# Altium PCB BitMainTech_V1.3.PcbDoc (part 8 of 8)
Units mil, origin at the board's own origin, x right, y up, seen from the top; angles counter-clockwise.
Board outline 9842.52 x 6082.68 mil, 4 copper layers (Top Layer, Mid-Layer 1, Mid-Layer 2, Bottom Layer); 987 components, 282 nets, 3694 pads, 3174 vias.
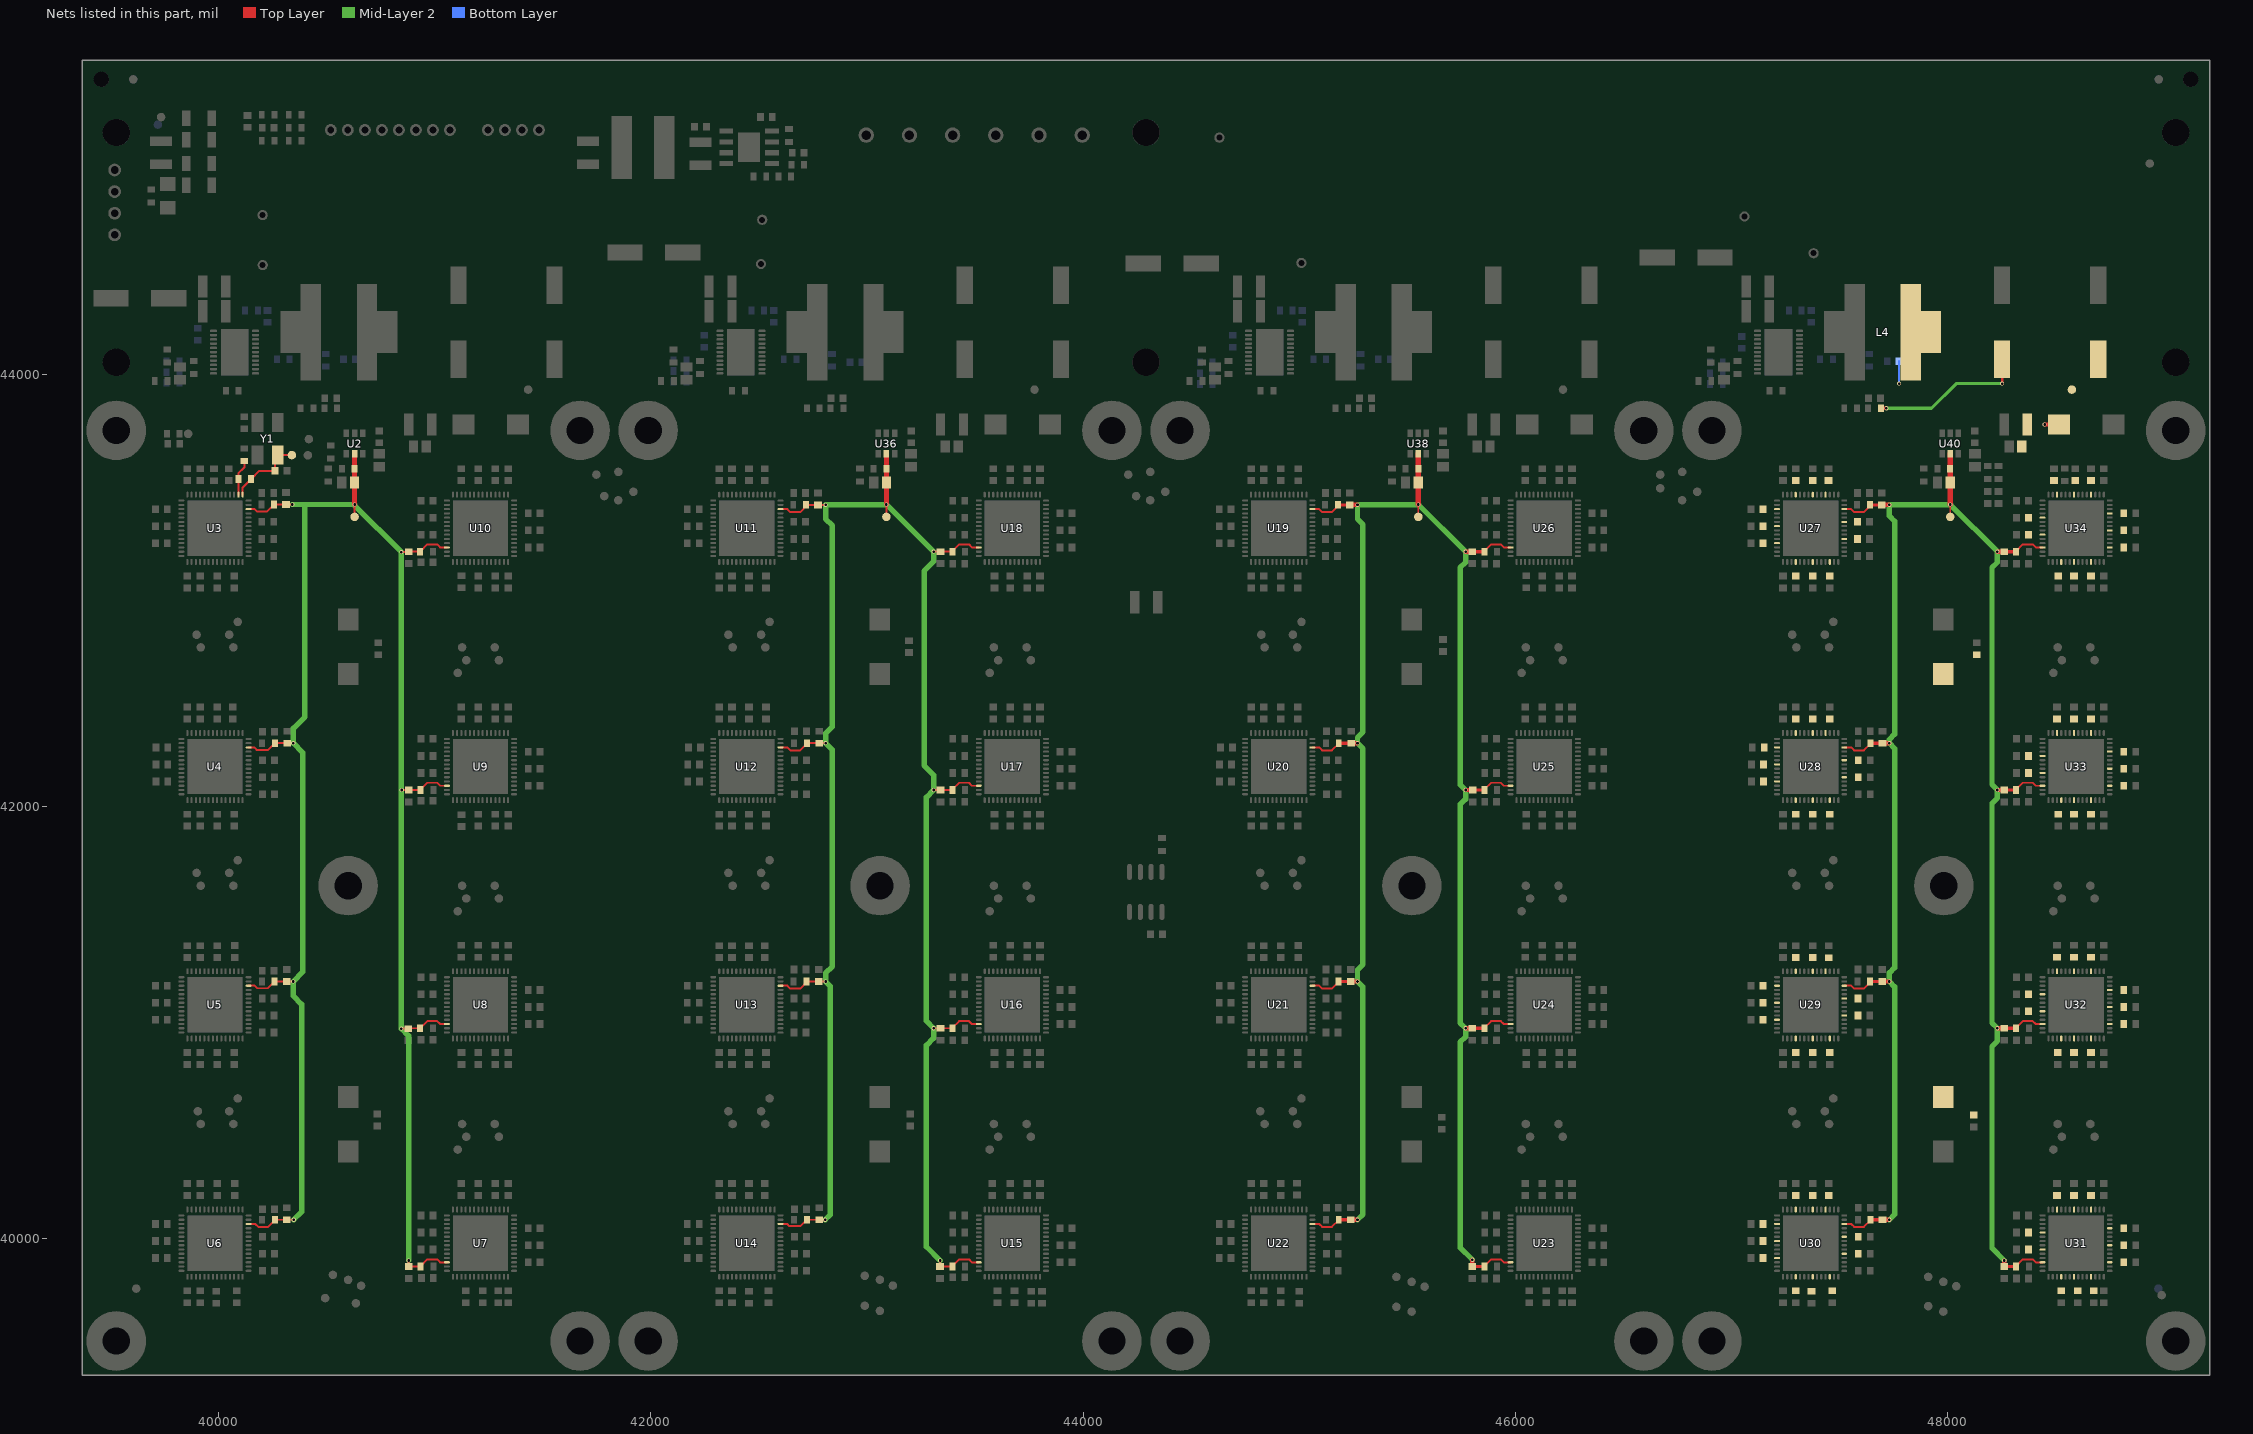
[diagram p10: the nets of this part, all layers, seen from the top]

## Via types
v1: diameter 19, hole 12, Top Layer to Bottom Layer, 1347 vias
v2: diameter 25.98, hole 12.99, Top Layer to Bottom Layer, 800 vias
v3: diameter 24, hole 16, Top Layer to Bottom Layer, 778 vias
v4: diameter 50, hole 28, Top Layer to Bottom Layer, 160 vias
v5: diameter 19.68, hole 11.81, Top Layer to Bottom Layer, 84 vias
v6: diameter 26, hole 18, Top Layer to Bottom Layer, 5 vias

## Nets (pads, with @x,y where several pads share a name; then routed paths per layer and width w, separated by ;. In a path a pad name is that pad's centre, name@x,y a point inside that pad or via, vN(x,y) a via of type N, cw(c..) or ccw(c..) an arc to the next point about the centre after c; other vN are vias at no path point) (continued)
VDD4: C416.1 C417.1 C418.2 C419.2 C440.2 C441.2 C442.2 C443.2 C444.2 C445.2 C446.2 C447.2 C448.2 C449.2 C450.2 C451.2 C452.2 C453.2 C454.2 C455.2 C456.2 C457.2 C458.2 C459.2 C460.2 C461.2 C462.2 C463.2 C464.2 C465.2 C466.2 C467.2 C468.2 C469.2 C470.2 C471.2 C472.2 C473.2 C474.2 C475.2 C476.2 C477.2 C478.2 C479.2 C480.2 C481.2 C482.2 C483.2 C504.2 C505.2 C506.2 C507.2 C508.2 C509.2 C510.2 C511.2 C512.2 C513.2 C514.2 C515.2 C516.2 C517.2 C518.2 C519.2 C520.2 C521.2 C522.2 C523.2 C524.2 C525.2 C526.2 C527.2 C528.2 C529.2 C530.2 C531.2 C532.2 C533.2 C534.2 C535.2 C536.2 C537.2 C538.2 C539.2 C540.2 C541.2 C542.2 C543.2 C544.2 C545.2 C546.2 C547.2 C580.1 C581.1 C582.1 C583.1 C587.2 C588.2 L4.2 R52.1 TP172.1 U27.4 U27.7 U27.11 U27.17 U27.21 U27.25 U27.32 U27.36 U27.40 U27.47 U27.51 U28.4 U28.7 U28.11 U28.17 U28.21 U28.25 U28.32 U28.36 U28.40 U28.47 U28.51 U29.4 U29.7 U29.11 U29.17 U29.21 U29.25 U29.32 U29.36 U29.40 U29.47 U29.51 U30.4 U30.7 U30.11 U30.17 U30.21 U30.25 U30.32 U30.36 U30.40 U30.47 U30.51 U31.4 U31.7 U31.11 U31.17 U31.21 U31.25 U31.32 U31.36 U31.40 U31.47 U31.51 U32.4 U32.7 U32.11 U32.17 U32.21 U32.25 U32.32 U32.36 U32.40 U32.47 U32.51 U33.4 U33.7 U33.11 U33.17 U33.21 U33.25 U33.32 U33.36 U33.40 U33.47 U33.51 U34.4 U34.7 U34.11 U34.17 U34.21 U34.25 U34.32 U34.36 U34.40 U34.47 U34.51 | length 845.5
  Top Layer w11: v1(48251.97,43956.69) C582.1@48251.97,44023.62
  Top Layer w15: R52.1@47690.94,43842.52 v1(47716.54,43842.52)
  Top Layer w20: v1(48448.82,43767.72) C583.1@48515.75,43767.72
  Mid-Layer 2 w15: v1(47716.54,43842.52) 47925.2,43842.52 48039.37,43956.69 v1(48251.97,43956.69)
  Bottom Layer w10: v1(47775.59,43956.69) C580.1@47775.59,44060
VPLL1: C16.2 C21.1 C23.1 C25.1 C27.1 C88.1 C90.1 C92.1 C94.1 FB1.2 FB2.2 FB3.2 FB4.2 FB5.2 FB6.2 FB7.2 FB8.2 R13.2 TP167.1 U2.5 U3.54 U4.54 U5.54 U6.54 U7.54 U8.54 U9.54 U10.54 | length 9395.2
  Top Layer w8: TP167.1@40629.92,43340 v1(40629.92,43397.64)
  Top Layer w9: U6.54@40139.76,40068.9 40171.26,40068.9 40185.04,40055.12 40230.32,40055.12 40263.78,40088.58 C27.1@40316.93,40088.58 v1(40348.43,40088.58) ; U5.54@40139.76,41171.26 40167.32,41171.26 40179.13,41159.45 40228.35,41159.45 FB3.2@40259.84,41190.94 ; U4.54@40139.76,42273.62 40165.35,42273.62 40177.17,42261.81 40230.32,42261.81 FB2.2@40261.81,42293.31 40314.96,42293.31 C90.1@40318.9,42293.31 v1(40346.46,42293.31) ; U3.54@40139.76,43375.98 40167.32,43375.98 40179.13,43364.17 40224.41,43364.17 FB1.2@40257.87,43397.64 40311.02,43397.64 C21.1@40312.99,43397.64 v1(40342.52,43397.64) ; FB3.2@40253.94,41190.94 40307.09,41190.94 v1(40346.46,41190.94) ; v1(40846.46,40972.44) C25.1@40877.95,40972.44 ; v1(40846.46,43177.17) C88.1@40877.95,43177.17 ; v1(40848.43,42076.77) C23.1@40879.92,42076.77 40933.07,42076.77 40966.54,42110.24 41011.81,42110.24 41025.59,42096.46 U9.54@41057.09,42096.46 ; C25.1@40877.95,40974.41 40879.92,40974.41 FB6.2@40933.07,40974.41 40966.54,41007.87 41011.81,41007.87 41025.59,40994.09 U8.54@41057.09,40994.09 ; v1(40879.92,39900) C94.1@40879.92,39872.05 40933.07,39872.05 40966.54,39905.51 41011.81,39905.51 41025.59,39891.73 U7.54@41057.09,39891.73 ; C88.1@40879.92,43179.13 FB8.2@40933.07,43179.13 40966.54,43212.6 41011.81,43212.6 41025.59,43198.82 U10.54@41057.09,43198.82
  Top Layer w24: v1(40629.92,43397.64) C16.2@40629.92,43500 R13.2@40629.92,43562.99 U2.5@40629.92,43631.89
  Mid-Layer 2 w25: v1(40342.52,43397.64) 40400,43397.64 ; v1(40348.43,40088.58) 40385,40125.16 40385,41085 40346.46,41123.54 v1(40346.46,41190.94) 40390,41234.49 40390,42249.76 v1(40346.46,42293.31) 40346.46,42361.46 40400,42415 40400,43397.64 ; v1(40879.92,39900) 40879.92,40938.98 v1(40846.46,40972.44) v1(40846.46,43177.17) 40629.92,43393.7 v1(40629.92,43397.64) 40400,43397.64
VPLL2: C156.1 C158.1 C160.1 C162.1 C220.1 C222.1 C224.1 C226.1 C563.2 FB9.2 FB10.2 FB11.2 FB12.2 FB13.2 FB14.2 FB15.2 FB16.2 R34.2 TP129.1 U11.54 U12.54 U13.54 U14.54 U15.54 U16.54 U17.54 U18.54 U36.5 | length 9460.3
  Top Layer w8: TP129.1@43090.55,43340 v1(43090.55,43397.64)
  Top Layer w9: U14.54@42600.39,40068.9 42631.1,40068.9 42641,40059 42692.86,40059 FB12.2@42722.44,40088.58 42775.59,40088.58 C162.1@42779.53,40088.58 v1(42807.09,40088.58) ; U13.54@42600.39,41171.26 42631.89,41171.26 42645.67,41157.48 42690.94,41157.48 42724.41,41190.94 C224.1@42777.56,41190.94 v1(42809.06,41190.94) ; U12.54@42600.39,42273.62 42631.89,42273.62 42645.67,42259.84 42690.94,42259.84 42724.41,42293.31 C222.1@42777.56,42293.31 ; U11.54@42600.39,43375.98 42631.89,43375.98 42645.67,43362.2 42690.94,43362.2 42724.41,43395.67 42777.56,43395.67 v1(42809.06,43395.67) ; C222.1@42779.53,42293.31 v1(42809.06,42293.31) ; v1(43309.05,40974.41) C160.1@43340.55,40974.41 43393.7,40974.41 43427.17,41007.87 43472.44,41007.87 43486.22,40994.09 U16.54@43517.72,40994.09 ; v1(43309.05,42076.77) C158.1@43340.55,42076.77 43393.7,42076.77 43427.17,42110.24 43472.44,42110.24 43486.22,42096.46 U17.54@43517.72,42096.46 ; v1(43309.05,43179.13) C220.1@43340.55,43179.13 43393.7,43179.13 43427.17,43212.6 43472.44,43212.6 43486.22,43198.82 U18.54@43517.72,43198.82 ; C226.1@43338.58,39872.05 v1(43338.58,39900) ; C226.1@43340.55,39872.05 43393.7,39872.05 43427.17,39905.51 43472.44,39905.51 43486.22,39891.73 U15.54@43517.72,39891.73
  Top Layer w24: v1(43090.55,43397.64) C563.2@43090.55,43500 R34.2@43090.55,43562.99 U36.5@43090.55,43631.89
  Mid-Layer 2 w25: v1(42807.09,40088.58) 42830,40111.5 42830,41170 v1(42809.06,41190.94) 42809.06,41229.06 42840,41260 42840,42262.36 v1(42809.06,42293.31) 42809.06,42339.06 42840,42370 42840,43300 42809.06,43330.94 v1(42809.06,43395.67) v1@43092.52,43395.67 ; v1(43090.55,43397.64) v1@43092.52,43395.67 ; v1(43338.58,39900) 43275,39963.58 43275,40895 43309.05,40929.05 v1(43309.05,40974.41) 43275,41008.46 43275,42042.72 v1(43309.05,42076.77) 43309.05,42145.95 43265,42190 43265,43090 43309.05,43134.05 v1(43309.05,43179.13) v1@43092.52,43395.67
VPLL3: C288.1 C290.1 C292.1 C294.1 C352.1 C354.1 C356.1 C358.1 C579.2 FB17.2 FB18.2 FB19.2 FB20.2 FB21.2 FB22.2 FB23.2 FB24.2 R48.2 TP171.1 U19.54 U20.54 U21.54 U22.54 U23.54 U24.54 U25.54 U26.54 U38.5 | length 9428.2
  Top Layer w8: TP171.1@45551.18,43340 v1(45551.18,43397.64)
  Top Layer w9: U22.54@45061.02,40068.9 45092.52,40068.9 45106.3,40055.12 45151.57,40055.12 FB20.2@45185.04,40088.58 ; U21.54@45061.02,41171.26 45092.52,41171.26 45106.3,41157.48 45151.57,41157.48 FB19.2@45185.04,41190.94 ; U20.54@45061.02,42273.62 45092.52,42273.62 45106.3,42259.84 45151.57,42259.84 FB18.2@45185.04,42293.31 ; U19.54@45061.02,43375.98 45092.52,43375.98 45106.3,43362.2 45151.57,43362.2 FB17.2@45185.04,43395.67 ; FB21.2@45854.33,39872.05 45887.8,39905.51 45933.07,39905.51 45946.85,39891.73 U23.54@45978.35,39891.73 ; FB22.2@45854.33,40974.41 45887.8,41007.87 45933.07,41007.87 45946.85,40994.09 U24.54@45978.35,40994.09 ; FB23.2@45854.33,42076.77 45887.8,42110.24 45933.07,42110.24 45946.85,42096.46 U25.54@45978.35,42096.46 ; FB24.2@45854.33,43179.13 45887.8,43212.6 45933.07,43212.6 45946.85,43198.82 U26.54@45978.35,43198.82
  Top Layer w15: FB20.2@45185.04,40088.58 C294.1@45238.17,40088.58 ; FB19.2@45185.04,41190.94 C356.1@45238.17,41190.94 ; FB18.2@45185.04,42293.31 C354.1@45238.19,42293.31 ; FB17.2@45185.04,43395.67 C288.1@45238.19,43395.67 ; C358.1@45801.16,39872.05 FB21.2@45854.33,39872.05 ; C292.1@45801.16,40974.41 FB22.2@45854.33,40974.41 ; C290.1@45801.18,42076.77 FB23.2@45854.33,42076.77 ; C352.1@45801.16,43179.13 FB24.2@45854.33,43179.13
  Top Layer w20: C294.1@45238.17,40088.58 v1(45269.69,40088.58) ; C356.1@45238.17,41190.94 v1(45269.69,41190.94) ; C288.1@45238.19,43395.67 v1(45269.69,43395.67) ; C354.1@45240.14,42293.31 v1(45269.69,42293.31) ; v1(45769.68,40974.41) C292.1@45801.16,40974.41 ; v1(45769.68,42076.77) C290.1@45801.18,42076.77 ; v1(45769.68,43179.13) C352.1@45801.16,43179.13 ; C358.1@45801.16,39872.05 v1(45801.16,39903.54)
  Top Layer w25: v1(45551.18,43397.64) C579.2@45551.18,43500 R48.2@45551.18,43562.99 U38.5@45551.18,43631.89
  Mid-Layer 2 w25: v1(45269.69,40088.58) 45295,40113.9 45295,41165.63 v1(45269.69,41190.94) 45269.69,41244.69 45295,41270 45295,42267.99 v1(45269.69,42293.31) 45269.69,42319.69 45295,42345 45295,43305 45269.69,43330.31 v1(45269.69,43395.67) v1@45553.15,43395.67 ; v1(45551.18,43397.64) v1@45553.15,43395.67 ; v1(45801.16,39903.54) 45745,39959.71 45745,40910 45769.68,40934.68 v1(45769.68,40974.41) 45745,40999.09 45745,42010 45769.68,42034.68 v1(45769.68,42076.77) 45745,42101.46 45745,43105 45769.68,43129.68 v1(45769.68,43179.13) v1@45553.15,43395.67
VPLL4: C420.1 C422.1 C424.1 C426.1 C484.1 C486.1 C488.1 C490.1 C595.2 FB25.2 FB26.2 FB27.2 FB28.2 FB29.2 FB30.2 FB31.2 FB32.2 R62.2 TP175.1 U27.54 U28.54 U29.54 U30.54 U31.54 U32.54 U33.54 U34.54 U40.5 | length 9430.2
  Top Layer w8: TP175.1@48011.81,43340 v1(48011.81,43397.64)
  Top Layer w9: U30.54@47521.65,40068.9 47553.15,40068.9 47566.93,40055.12 47612.2,40055.12 FB28.2@47645.67,40088.58 ; U29.54@47521.65,41171.26 47553.15,41171.26 47566.93,41157.48 47612.2,41157.48 FB27.2@47645.67,41190.94 ; U28.54@47521.65,42273.62 47553.15,42273.62 47566.93,42259.84 47612.2,42259.84 FB26.2@47645.67,42293.31 ; U27.54@47521.65,43375.98 47553.15,43375.98 47566.93,43362.2 47612.2,43362.2 FB25.2@47645.67,43395.67 ; FB29.2@48314.96,39872.05 48348.43,39905.51 48393.7,39905.51 48407.48,39891.73 U31.54@48438.98,39891.73 ; FB30.2@48314.96,40974.41 48348.43,41007.87 48393.7,41007.87 48407.48,40994.09 U32.54@48438.98,40994.09 ; FB31.2@48314.96,42076.77 48348.43,42110.24 48393.7,42110.24 48407.48,42096.46 U33.54@48438.98,42096.46 ; FB32.2@48314.96,43179.13 48348.43,43212.6 48393.7,43212.6 48407.48,43198.82 U34.54@48438.98,43198.82
  Top Layer w15: FB28.2@47645.67,40088.58 C426.1@47698.82,40088.58 ; FB27.2@47645.67,41190.94 C488.1@47698.82,41190.94 ; FB26.2@47645.67,42293.31 C486.1@47698.82,42293.31 ; FB25.2@47645.67,43395.67 C420.1@47698.82,43395.67 ; C490.1@48261.81,39872.05 FB29.2@48314.96,39872.05 ; C424.1@48261.81,40974.41 FB30.2@48314.96,40974.41 ; C422.1@48261.81,42076.77 FB31.2@48314.96,42076.77 ; C484.1@48261.81,43179.13 FB32.2@48314.96,43179.13
  Top Layer w20: C426.1@47698.82,40088.58 v1(47730.32,40088.58) ; C488.1@47698.82,41190.94 v1(47730.32,41190.94) ; C486.1@47698.82,42293.31 v1(47730.32,42293.31) ; C420.1@47698.82,43395.67 v1(47730.32,43395.67) ; v1(48230.31,40974.41) C424.1@48261.81,40974.41 ; v1(48230.31,42076.77) C422.1@48261.81,42076.77 ; v1(48230.31,43179.13) C484.1@48261.81,43179.13 ; C490.1@48261.81,39872.05 v1(48261.81,39900)
  Top Layer w25: v1(48011.81,43397.64) C595.2@48011.81,43500 R62.2@48011.81,43562.99 U40.5@48011.81,43631.89
  Mid-Layer 2 w25: v1(47730.32,40088.58) 47755,40113.27 47755,41166.26 v1(47730.32,41190.94) 47730.32,41230.32 47755,41255 47755,42268.62 v1(47730.32,42293.31) 47730.32,42310.32 47755,42335 47755,43320 47730.32,43344.68 v1(47730.32,43395.67) v1@48013.78,43395.67 ; v1(48011.81,43397.64) v1@48013.78,43395.67 ; v1(48261.81,39900) 48205,39956.81 48205,40890 48230.31,40915.31 v1(48230.31,40974.41) 48205,40999.72 48205,42015 48230.31,42040.31 v1(48230.31,42076.77) 48205,42102.09 48205,43105 48230.31,43130.31 v1(48230.31,43179.13) v1@48013.78,43395.67
XIN: C29.1 R16.2 TP25.1 U3.1 Y1.1 | length 340.3
  Top Layer w10: U3.1@40112.2,43442.91 40112.2,43476.38 R16.2@40151.57,43515.75 40188.98,43553.15 C29.1@40261.81,43553.15 Y1.1@40261.81,43614.17 ; Y1.1@40275.59,43625.98 TP25.1@40340,43625.98
XOUT: R16.1 R17.1 U3.2 | length 166.9
  Top Layer w10: U3.2@40092.52,43442.91 R16.1@40092.52,43515.75 40092.52,43541.34 40120.08,43568.9 R17.1@40120.08,43598.43
pads on no net: M1.0 M2.0 M3.0 M27.0 M28.0 M32.0 MAKE1.0 MAKE2.0 MAKE3.0 MAKE4.0 MAKE5.0 MAKE6.0 MAKE7.0 MAKE8.0 MAKE9.0 MAKE10.0 U1.5 U3.44 U3.48 U3.49 U4.2 U4.44 U4.48 U4.49 U5.2 U5.44 U5.48 U5.49 U6.2 U6.44 U6.48 U6.49 U7.2 U7.44 U7.48 U7.49 U8.2 U8.44 U8.48 U8.49 U9.2 U9.44 U9.48 U9.49 U10.2 U10.44 U10.48 U10.49 U11.2 U11.44 U11.48 U11.49 U12.2 U12.44 U12.48 U12.49 U13.2 U13.44 U13.48 U13.49 U14.2 U14.44 U14.48 U14.49 U15.2 U15.44 U15.48 U15.49 U16.2 U16.44 U16.48 U16.49 U17.2 U17.44 U17.48 U17.49 U18.2 U18.44 U18.48 U18.49 U19.2 U19.44 U19.48 U19.49 U20.2 U20.44 U20.48 U20.49 U21.2 U21.44 U21.48 U21.49 U22.2 U22.44 U22.48 U22.49 U23.2 U23.44 U23.48 U23.49 U24.2 U24.44 U24.48 U24.49 U25.2 U25.44 U25.48 U25.49 U26.2 U26.44 U26.48 U26.49 U27.2 U27.44 U27.48 U27.49 U28.2 U28.44 U28.48 U28.49 U29.2 U29.44 U29.48 U29.49 U30.2 U30.44 U30.48 U30.49 U31.2 U31.44 U31.48 U31.49 U32.2 U32.44 U32.48 U32.49 U33.2 U33.44 U33.48 U33.49 U34.2 U34.33 U34.34 U34.38 U34.39 U34.44 U37.5 U39.5 U41.5 U42.3 Y1.2 Y1.4

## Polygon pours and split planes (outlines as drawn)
VDD2 on Top Layer "GND1" (solid, remove dead copper, pour order 32): 42960,44420 43155,44420 43350.63,44224.37 44225.63,44224.37 44275,44175 44275,39385 41845,39385 41845,43885 42905,43885 42960,43940
GND on Top Layer "GND1" (solid, remove dead copper, pour order 31): 49200,45260 47155,45260 47155,44085 46865,44085 46785,44165 46785,44470 46620,44635 44935,44635 44800,44500 44800,44085 44460,44085 44460,44420 44245,44635 42500,44635 42355,44490 42355,44090 42010,44090 42010,44495 41870,44635 40150,44635 40010,44495 40010,44080 39625,44080 39625,44705 39390,44705 39390,43910 40590,43910 40605,43925 40605,44440 40790,44440 40990,44240 41679.25,44240 41845,44074.25 41845,43910 42910,43910 42945,43945 42945,44435 43160,44435 43355,44240 44230.79,44240 44378.78,44092.01 44378.78,44040.79 44305,43967.01 44305,43915 45355,43915 45385,43945 45385,44435 45715,44435 45910,44240 46570,44240 46765,44045 46765,43910 47710,43910 47745,43945 47745,44435 47990,44435 48185,44240 49200,44240
+12V on Top Layer "GND1" (solid, remove dead copper, pour order 30): 47140,45259.28 47140,44095 46875,44095 46800,44170 46800,44475 46625,44650 44930,44650 44785,44505 44785,44095 44475.24,44095 44475,44095.24 44475,44425 44250,44650 42490,44650 42340,44500 42340,44095 42330,44105 42025,44105 42025,44500 41875,44650 40145,44650 39995,44500 39995,44095 39640,44095 39640,44550 39640,44551.11 39915,44826.11 39915,45010 40560,45010 40600,45050 41475,45050 41615,44910 41755,44910 41810,44855 42740,44855 42740,45259.28
FANGND on Top Layer "GND1" (solid, pour order 25): 39885,45260 39885,45040 39675,45040 39650,45015 39650,44925 39625,44900 39390,44900 39390,45260
GND on Top Layer "GND1" (solid, pour order 24): 42725,45260 42725,44870 41815,44870 41760,44925 41620,44925 41475,45070 40600,45070 40555,45025 39915,45025 39915,45250 39915,45255 39915,45260
VDD1 on Top Layer "GND1" (solid, remove dead copper, pour order 23): 40620,44425 40785,44425 40985,44225 41665,44225 41815,44075 41815,39385 39385,39385 39385,43885 40595,43885 40620,43910 40620,44425
VDD3 on Top Layer "GND1" (solid, remove dead copper, pour order 22): 44305,43885 45345,43885 45400,43940 45400,44420 45711.26,44420 45906.26,44225 46565,44225 46735,44055 46735,39385 44305,39385
LL2 on Top Layer "GND1" (solid, pour order 21): 42820,43970 42820,44420.16 42818.9,44421.26 42626.26,44421.26 42495,44290 42496.06,44288.94 42496.06,44096.46 42718.54,44096.46 42720,44095 42720,43970
NetC549_2 on Top Layer "GND1" (solid, pour order 18): 39885,45020 39680,45020 39670,45010 39670,44925 39670,44920 39670,44915 39640,44885 39460,44885 39460,44805 39625,44805 39660,44840 39885,44840
VDD4 on Top Layer "GND1" (solid, remove dead copper, pour order 19): 49195,44225 49200,44220 49200,39385 46770,39385 46770,43885 47710,43885 47760,43935 47760,44420 47985,44420 48180,44225
no net on Top Layer "GND1" (solid, pour order 20): 49212.6,45452.76 49212.6,45275.59 39370.08,45275.59 39370.08,45452.76
GND on Mid-Layer 2 "GND1" (solid, remove dead copper, pour order 27): 39385,44085 40010,44085 40010,44495 40150,44635 41870,44635 42010,44495 42010,44100 42355,44100 42355,44490 42500,44635 44245,44635 44460,44420 44460,44085 44800,44085 44800,44500 44935,44635 46620,44635 46785,44470 46785,44165 46865,44085 47155,44085 47155,45260 49200,45260 49200,39385 39385,39385
+12V on Mid-Layer 2 "GND1" (solid, remove dead copper, pour order 26): 39995,44100 39385,44100 39385,45260 47140,45260 47140,44100 46870,44100 46800,44170 46800,44475 46625,44650 44930,44650 44785,44505 44785,44100 44475,44100 44475,44425 44250,44650 42490,44650 42340,44500 42340,44115 42025,44115 42025,44500 41875,44650 40145,44650 39995,44500 39995,44100
GND on Mid-Layer 1 "GND1" (solid, pour order 28): 39370.08,45275.59 49212.6,45275.59 49212.6,39370.08 39370.08,39370.08
GND on Bottom Layer "GND1" (solid, remove dead copper, pour order 29): 39370.08,45275.59 49212.6,45275.59 49212.6,39370.08 39370.08,39370.08
no net on Bottom Layer "GND1" (solid, pour order 17): 39370.08,45452.76 49212.6,45452.76 49212.6,45275.59 39370.08,45275.59

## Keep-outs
Keep-Out Layer:
  lines w7.99: 39370.08,45275.59 39370.08,45452.76 49212.6,45452.76 49212.6,45275.59
  lines w8: 39370.08,39370.08 39370.08,43897.64 39370.08,45275.59 49212.6,45275.59 49212.6,39370.08 39370.08,39370.08

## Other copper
Top Layer:
  rectangle net NetC551_2: 42075,44905 42160,45135
  rectangle net NetC551_2: 42135,45010 42386.49,45040
  rectangle net LL1: 40153.54,44096.46 40476.38,44421.26
  rectangle net +12V: 39795.28,44011.81 39850.39,44137.8
  rectangle net +12V: 42137.8,44011.81 42192.91,44137.8
  rectangle net +12V: 44582.68,44011.81 44637.8,44137.8
  rectangle net LL3: 44940.94,44096.46 45263.78,44421.26
  rectangle net +12V: 46937.01,44011.81 46992.13,44137.8
  rectangle net LL4: 47295.28,44096.46 47618.11,44421.26
  region net NetC551_2: 42070,45195 42070,45120 42220,45120 42220,45195
  pour cut-out: 47671.73,43865 47726.73,43865 47726.73,43820 47671.73,43820
  pour cut-out: 45317.4,43865 45372.4,43865 45372.4,43820 45317.4,43820
  pour cut-out: 42872.52,43865 42927.52,43865 42927.52,43820 42872.52,43820
  pour cut-out: 49092.56,45030 49142.56,45080 49142.56,45155 49092.56,45205 49012.56,45205 48962.56,45150 48962.56,45080 49012.56,45030
  pour cut-out: 49092.56,43967.01 49142.56,44017.01 49142.56,44092.01 49092.56,44142.01 49012.56,44142.01 48962.56,44087.01 48962.56,44017.01 49012.56,43967.01
  pour cut-out: 44328.78,43967.01 44378.78,44017.01 44378.78,44092.01 44328.78,44142.01 44248.78,44142.01 44198.78,44087.01 44198.78,44017.01 44248.78,43967.01
  pour cut-out: 44328.78,45030 44378.78,45080 44378.78,45155 44328.78,45205 44248.78,45205 44198.78,45150 44198.78,45080 44248.78,45030
  pour cut-out: 39565,45030 39615,45080 39615,45155 39565,45205 39485,45205 39435,45150 39435,45080 39485,45030
  pour cut-out: 44185,41775 44395,41775 44395,41440 44185,41440
  pour cut-out: 39565,43967.01 39615,44017.01 39615,44092.01 39565,44142.01 39485,44142.01 39435,44087.01 39435,44017.01 39485,43967.01
  pour cut-out: 40530,43865 40585,43865 40585,43820 40530,43820
  pour cut-out: 42160,45040 42160,45120 42385,45120 42386.49,45118.51 42386.49,45040
Mid-Layer 1:
  pour cut-out: 49092.56,45030 49142.56,45080 49142.56,45155 49092.56,45205 49012.56,45205 48962.56,45150 48962.56,45080 49012.56,45030
  pour cut-out: 49092.56,43967.01 49142.56,44017.01 49142.56,44092.01 49092.56,44142.01 49012.56,44142.01 48962.56,44087.01 48962.56,44017.01 49012.56,43967.01
  pour cut-out: 44328.78,43967.01 44378.78,44017.01 44378.78,44092.01 44328.78,44142.01 44248.78,44142.01 44198.78,44087.01 44198.78,44017.01 44248.78,43967.01
  pour cut-out: 44328.78,45030 44378.78,45080 44378.78,45155 44328.78,45205 44248.78,45205 44198.78,45150 44198.78,45080 44248.78,45030
  pour cut-out: 39565,43967.01 39615,44017.01 39615,44092.01 39565,44142.01 39485,44142.01 39435,44087.01 39435,44017.01 39485,43967.01
  pour cut-out: 39565,45030 39615,45080 39615,45155 39565,45205 39485,45205 39435,45150 39435,45080 39485,45030
Mid-Layer 2:
  pour cut-out: 49092.56,45030 49142.56,45080 49142.56,45155 49092.56,45205 49012.56,45205 48962.56,45150 48962.56,45080 49012.56,45030
  pour cut-out: 49092.56,43967.01 49142.56,44017.01 49142.56,44092.01 49092.56,44142.01 49012.56,44142.01 48962.56,44087.01 48962.56,44017.01 49012.56,43967.01
  pour cut-out: 44328.78,43967.01 44378.78,44017.01 44378.78,44092.01 44328.78,44142.01 44248.78,44142.01 44198.78,44087.01 44198.78,44017.01 44248.78,43967.01
  pour cut-out: 44328.78,45030 44378.78,45080 44378.78,45155 44328.78,45205 44248.78,45205 44198.78,45150 44198.78,45080 44248.78,45030
  pour cut-out: 39565,43967.01 39615,44017.01 39615,44092.01 39565,44142.01 39485,44142.01 39435,44087.01 39435,44017.01 39485,43967.01
  pour cut-out: 39565,45030 39615,45080 39615,45155 39565,45205 39485,45205 39435,45150 39435,45080 39485,45030
Bottom Layer:
  pour cut-out: 49092.56,45030 49142.56,45080 49142.56,45155 49092.56,45205 49012.56,45205 48962.56,45150 48962.56,45080 49012.56,45030
  pour cut-out: 49092.56,43967.01 49142.56,44017.01 49142.56,44092.01 49092.56,44142.01 49012.56,44142.01 48962.56,44087.01 48962.56,44017.01 49012.56,43967.01
  pour cut-out: 44328.78,43967.01 44378.78,44017.01 44378.78,44092.01 44328.78,44142.01 44248.78,44142.01 44198.78,44087.01 44198.78,44017.01 44248.78,43967.01
  pour cut-out: 44328.78,45030 44378.78,45080 44378.78,45155 44328.78,45205 44248.78,45205 44198.78,45150 44198.78,45080 44248.78,45030
  pour cut-out: 39565,43967.01 39615,44017.01 39615,44092.01 39565,44142.01 39485,44142.01 39435,44087.01 39435,44017.01 39485,43967.01
  pour cut-out: 39565,45030 39615,45080 39615,45155 39565,45205 39485,45205 39435,45150 39435,45080 39485,45030

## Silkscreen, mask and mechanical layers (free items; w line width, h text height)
Top Overlay:
  lines w7.99: 42896.85,44956.3 42896.85,44710 43496.85,44710 ; 43496.85,45020 43496.85,44710 ; 44096.06,44956.3 44096.06,44710 43496.85,44710
  lines w10: 44945.2,44740 46559.37,44740 46559.37,45173.07 44945.2,45173.07 44945.2,44740
  text "V1.3" at 48610,44865 h40
  text "BitMainTech" at 47895,44765 h60
  text "2013/11/18" at 47915,44660 h60
Mechanical 1:
  lines w8: 39370.08,39980.32 49212.6,39980.32 ; 39370.08,41082.68 49212.6,41082.68 ; 39370.08,42185.04 49212.6,42185.04 ; 39370.08,43287.4 49212.6,43287.4 ; 39370.08,43897.64 49212.6,43897.64 ; 39984.25,39370.08 39984.25,43897.64 ; 41212.6,39370.08 41212.6,43897.64 ; 41830.71,39370.08 41830.71,44881.89 ; 42444.88,39370.08 42444.88,43897.64 ; 43673.23,39370.08 43673.23,43897.64 ; 44291.34,39370.08 44291.34,44881.89 ; 44905.51,39370.08 44905.51,43897.64 ; 46133.86,39370.08 46133.86,43897.64 ; 46751.97,39370.08 46751.97,44881.89 ; 47366.14,39370.08 47366.14,43897.64 ; 48594.49,39370.08 48594.49,43897.64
